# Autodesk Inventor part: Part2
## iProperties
Shininess: 77.0
Angle Display Precision: 2
Document Length Units: 11269
Document Angle Units: 11279
Document Time Units: 11290
Document Mass Units: 11283
Document Length Units Precision: 3
Document Angle Units Precision: 2
Created: 2001-12
Part Number: Part2
Document SubType Name: Modeling
Designer: CADSoft
Density: 0.0
Volumn: 0.0
Area: 0.0
PropertySet Name: Model Information
Control State: 0
Master: False
Checked Out: False
Author: CADSoft
